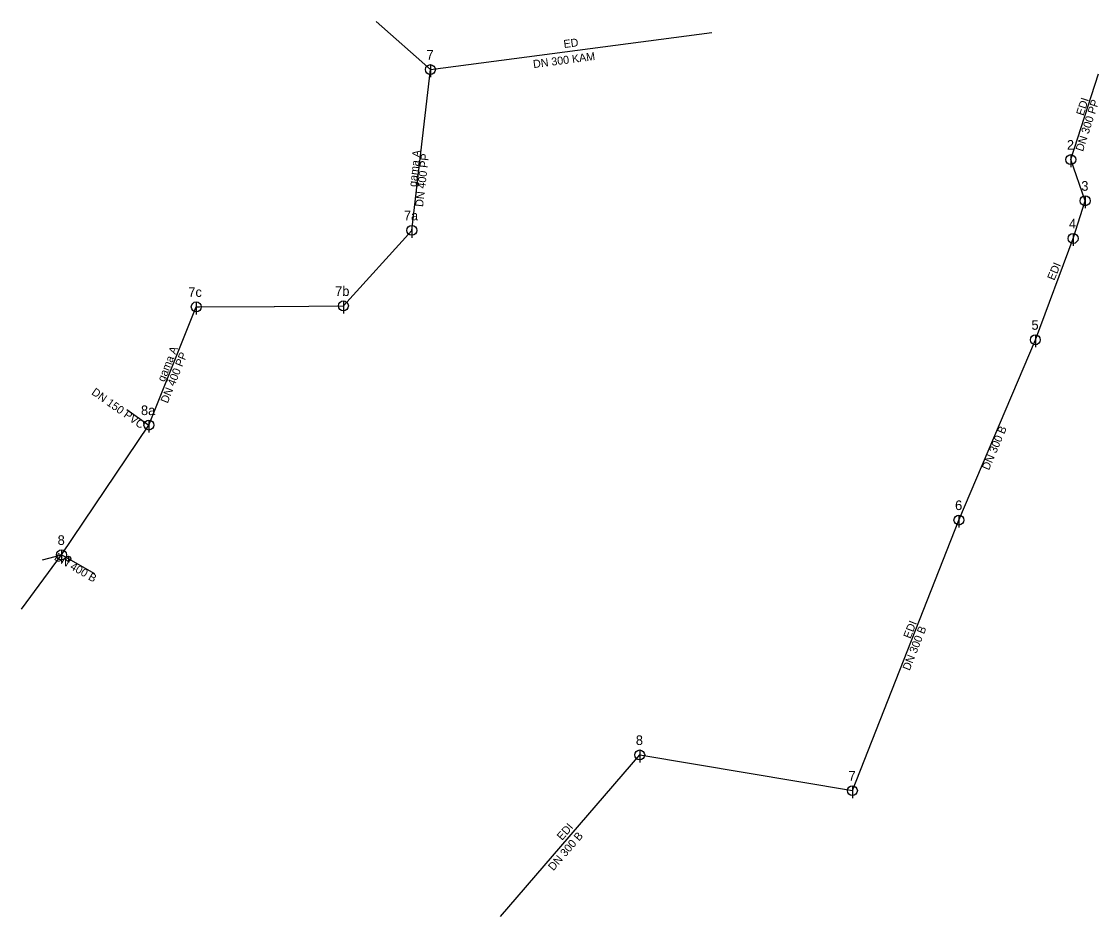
# Model space of a CAD drawing. Extents: x -466037 to -465821, y -1092768 to -1092588.
import ezdxf

# ---------------------------------------------------------------- set-up
doc = ezdxf.new("R2010")
doc.units = 0
for name, color, linetype in [('_kanalizacni_chranicka_', 7, 'Continuous'), ('_pripojka_kanal_jednotna_prevzato_z_dokumentace_', 7, 'Continuous'), ('_pripojka_kanal_jednotna_priblizne_', 7, 'Continuous'), ('_stoka_jednotna_provozovana_prevzato_z_dokumentace_', 7, 'Continuous'), ('_stoka_jednotna_smvak_prevzato_z_dokumentace_', 7, 'Continuous'), ('Default', 7, 'Continuous'), ('MoLevel 119', 7, 'Continuous'), ('MoLevel 120', 7, 'Continuous'), ('MoLevel 124', 7, 'Continuous'), ('MoLevel 126', 7, 'Continuous'), ('MoLevel 57', 7, 'Continuous'), ('MoLevel 68', 7, 'Continuous'), ('MoLevel 69', 7, 'Continuous'), ('MoLevel 76', 7, 'Continuous'), ('MoLevel 77', 7, 'Continuous')]:
    doc.layers.add(name, color=color, linetype=linetype)

# ---------------------------------------------------------------- blocks, each defined once
blk = doc.blocks.new('_sachta_kanal_prip_')
at = {"layer": 'Default'}
blk.add_line((0, 0.00005), (0, -0.000075), dxfattribs=at)
blk.add_circle((0, 0), 0.00005, dxfattribs=at)
blk = doc.blocks.new('_sachta_kanal_prevzato_z_dokumentace_')
at = {"layer": 'Default'}
blk.add_line((0, 0.00005), (0, -0.000075), dxfattribs=at)
blk.add_circle((0, 0), 0.00005, dxfattribs=at)

msp = doc.modelspace()

# ---------------------------------------------------------------- linework, layer by layer
at = {"layer": '_kanalizacni_chranicka_'}
msp.add_line((-466001.31, -1092645.26), (-465986.26, -1092645.16), dxfattribs=at)
at = {"layer": '_pripojka_kanal_jednotna_prevzato_z_dokumentace_'}
for p, q in [((-466015.84, -1092665.85), (-466011.41, -1092668.97)), ((-466032.76, -1092696.03), (-466028.95, -1092695.02)), ((-466027.58, -1092695.79), (-466028.95, -1092695.02))]:
    msp.add_line(p, q, dxfattribs=at)
at = {"layer": '_pripojka_kanal_jednotna_priblizne_'}
msp.add_line((-466022.3, -1092698.85), (-466027.58, -1092695.79), dxfattribs=at)
at = {"layer": '_stoka_jednotna_provozovana_prevzato_z_dokumentace_'}
for p, q in [((-465965.82, -1092588.02), (-465954.96, -1092597.66)), ((-465954.96, -1092597.66), (-465898.52, -1092590.25)), ((-465826.5, -1092615.72), (-465820.95, -1092598.5)), ((-465823.62, -1092623.97), (-465826.5, -1092615.72)), ((-465826.04, -1092631.53), (-465823.62, -1092623.97)), ((-465833.61, -1092651.86), (-465826.04, -1092631.53)), ((-465848.93, -1092688.03), (-465833.61, -1092651.86)), ((-465870.31, -1092742.32), (-465848.93, -1092688.03)), ((-465940.91, -1092767.56), (-465912.97, -1092735.16)), ((-465912.97, -1092735.16), (-465870.31, -1092742.32))]:
    msp.add_line(p, q, dxfattribs=at)
at = {"layer": '_stoka_jednotna_smvak_prevzato_z_dokumentace_'}
for p, q in [((-465958.68, -1092629.91), (-465954.96, -1092597.66)), ((-465972.41, -1092645.07), (-465958.68, -1092629.91)), ((-466011.41, -1092668.97), (-466001.92, -1092645.26)), ((-466028.95, -1092695.02), (-466011.41, -1092668.97)), ((-466036.97, -1092705.91), (-466028.95, -1092695.02))]:
    msp.add_line(p, q, dxfattribs=at)
msp.add_lwpolyline([(-466001.92, -1092645.26), (-466001.26, -1092645.26), (-465986.27, -1092645.16), (-465972.41, -1092645.07)], dxfattribs=at)

# ---------------------------------------------------------------- block references
at = {"layer": 'MoLevel 119', "xscale": 20000, "yscale": 20000}
for p in [(-465954.96, -1092597.66), (-465826.5, -1092615.72), (-465823.62, -1092623.97), (-465958.68, -1092629.91), (-465826.04, -1092631.53), (-466001.92, -1092645.26), (-465972.41, -1092645.07), (-465833.61, -1092651.86), (-466011.41, -1092668.97), (-465848.93, -1092688.03), (-466028.95, -1092695.02), (-465912.97, -1092735.16), (-465870.31, -1092742.32)]:
    msp.add_blockref('_sachta_kanal_prevzato_z_dokumentace_', p, dxfattribs=at)
at = {"layer": 'MoLevel 57', "xscale": 10000, "yscale": 10000}
msp.add_blockref('_sachta_kanal_prip_', (-466027.58, -1092695.79), dxfattribs=at)

# ---------------------------------------------------------------- texts
at = {"layer": 'MoLevel 120'}
for s, height, p in [('7', 1.93, (-465955.74, -1092595.66)), ('2', 1.93, (-465827.28, -1092613.72)), ('3', 1.93, (-465824.4, -1092621.97)), ('7a', 1.926, (-465960.28, -1092627.91)), ('4', 1.93, (-465826.87, -1092629.53)), ('7c', 1.926, (-466003.52, -1092643.26)), ('7b', 1.926, (-465974.06, -1092643.07)), ('5', 1.93, (-465834.39, -1092649.86)), ('8a', 1.926, (-466013.01, -1092666.97)), ('6', 1.93, (-465849.71, -1092686.03)), ('8', 1.93, (-466029.73, -1092693.02)), ('8', 1.93, (-465913.75, -1092733.16)), ('7', 1.93, (-465871.09, -1092740.32))]:
    msp.add_text(s, height=height, dxfattribs=at).set_placement(p)
at = {"layer": 'MoLevel 124'}
msp.add_text('DN 400 B', height=1.605, rotation=329.8794, dxfattribs=at).set_placement((-466030.55, -1092695.92))
at = {"layer": 'MoLevel 126'}
msp.add_text('DN 150 PVC', height=1.605, rotation=324.8102, dxfattribs=at).set_placement((-466023.07, -1092662.71))
at = {"layer": 'MoLevel 68'}
for rotation, p in [(83.4193, (-465956.44, -1092625.27)), (68.1861, (-466007.66, -1092664.72))]:
    msp.add_text('DN 400 PP', height=1.605, rotation=rotation, dxfattribs=at).set_placement(p)
at = {"layer": 'MoLevel 69'}
for rotation, p in [(83.4193, (-465957.77, -1092621.25)), (68.1861, (-466008.31, -1092660.43))]:
    msp.add_text('gama A', height=1.605, rotation=rotation, dxfattribs=at).set_placement(p)
at = {"layer": 'MoLevel 76'}
for s, rotation, p in [('DN 300 KAM', 7.4796, (-465934.26, -1092597.36)), ('DN 300 PP', 72.1359, (-465824.07, -1092614.2)), ('DN 300 B', 67.0439, (-465842.93, -1092678.15)), ('DN 300 B', 68.5049, (-465858.83, -1092718.35)), ('DN 300 B', 49.2273, (-465930.29, -1092758.5))]:
    msp.add_text(s, height=1.605, rotation=rotation, dxfattribs=at).set_placement(p)
at = {"layer": 'MoLevel 77'}
for s, rotation, p in [('ED', 7.4796, (-465928.14, -1092593.34)), ('EDI', 72.1359, (-465823.95, -1092607.01)), ('EDI', 67.0439, (-465829.82, -1092640.07)), ('EDI', 68.5049, (-465858.66, -1092711.94)), ('EDI', 49.2273, (-465928.54, -1092752.41))]:
    msp.add_text(s, height=1.605, rotation=rotation, dxfattribs=at).set_placement(p)

doc.saveas('drawing.dxf')
